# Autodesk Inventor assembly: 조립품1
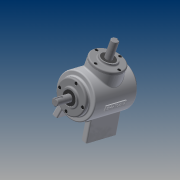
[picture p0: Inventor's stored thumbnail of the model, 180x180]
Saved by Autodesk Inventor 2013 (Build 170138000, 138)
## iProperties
Created: 2015-01
Part Number: 조립품1
Document SubType Name: Assembly
Designer: cad8
Author: cad8
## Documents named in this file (15)
- C:\Documents and Settings\cad8\바탕 화면\450106V1020\조립품1.iam
- C:\Documents and Settings\cad8\바탕 화면\450106V1020\오일실.ipt
- C:\Documents and Settings\cad8\바탕 화면\450106V1020\커버2.ipt
- C:\Documents and Settings\cad8\바탕 화면\450106V1020\커버.ipt
- C:\Documents and Settings\cad8\바탕 화면\450106V1020\키 4x4.ipt
- C:\Documents and Settings\cad8\바탕 화면\450106V1020\키 5x5.ipt
- C:\Documents and Settings\cad8\바탕 화면\450106V1020\M4.ipt
- C:\Documents and Settings\cad8\바탕 화면\450106V1020\메인 베벨기어.ipt
- C:\Documents and Settings\cad8\바탕 화면\450106V1020\메인 축.ipt
- 메인 축.ipt
- C:\Documents and Settings\cad8\바탕 화면\450106V1020\베어링 6203.ipt
- C:\Documents and Settings\cad8\바탕 화면\450106V1020\본체.ipt
- C:\Documents and Settings\cad8\바탕 화면\450106V1020\서브 베벨기어.ipt
- C:\Documents and Settings\cad8\바탕 화면\450106V1020\서브 축.ipt
- 서브 축.ipt
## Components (12 placed, 1 different names)
1. M4:1
2. M4:2
3. M4:3
4. M4:4
5. M4:5
6. M4:7
7. M4:8
8. M4:9
9. M4:6
10. M4:10
11. M4:11
12. M4:12
